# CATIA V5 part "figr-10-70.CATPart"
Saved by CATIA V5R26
Part number: Part1
Bounding box of the stored display mesh (mm): x -80.563 to 63.541, y -72 to 69, z -55 to 56
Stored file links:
  D:\_Deepak\CATIA\CATIA V5-6R2016_Deepak\Resources\Part files\Partfiles\c10_catia_v5_6r2016_prt\figr-10-70.CATPart
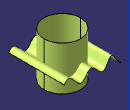
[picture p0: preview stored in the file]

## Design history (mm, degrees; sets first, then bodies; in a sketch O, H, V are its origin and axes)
Set1
  Sketch1 on xy-plane, origin (0, 0, 0), H (-1, 0, 0), V (0, -1, 0)
    circle A1 centre (0, 0) radius 45.985
  Extrude1: Element1 Sketch1, Lim1 56, Lim2 55, Direction xy-plane
  Sketch2 on zx-plane, origin (0, 0, 0), H (1, 0, 0), V (0, 0, -1)
    spline S1 through (-80.5635, 24.8913) (-73.6025, 19.8803) (-54.8525, -3.3629) (-35.1982, 19.8803) (-2.6271, -1.6506) (16.6996, 17.2854) (52.4104, -6.7877) (63.5409, 1.5862)
  Extrude2: Element1 Sketch2, Lim1 72, Lim2 69, Direction Sketch1.V
Body1 (main body)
